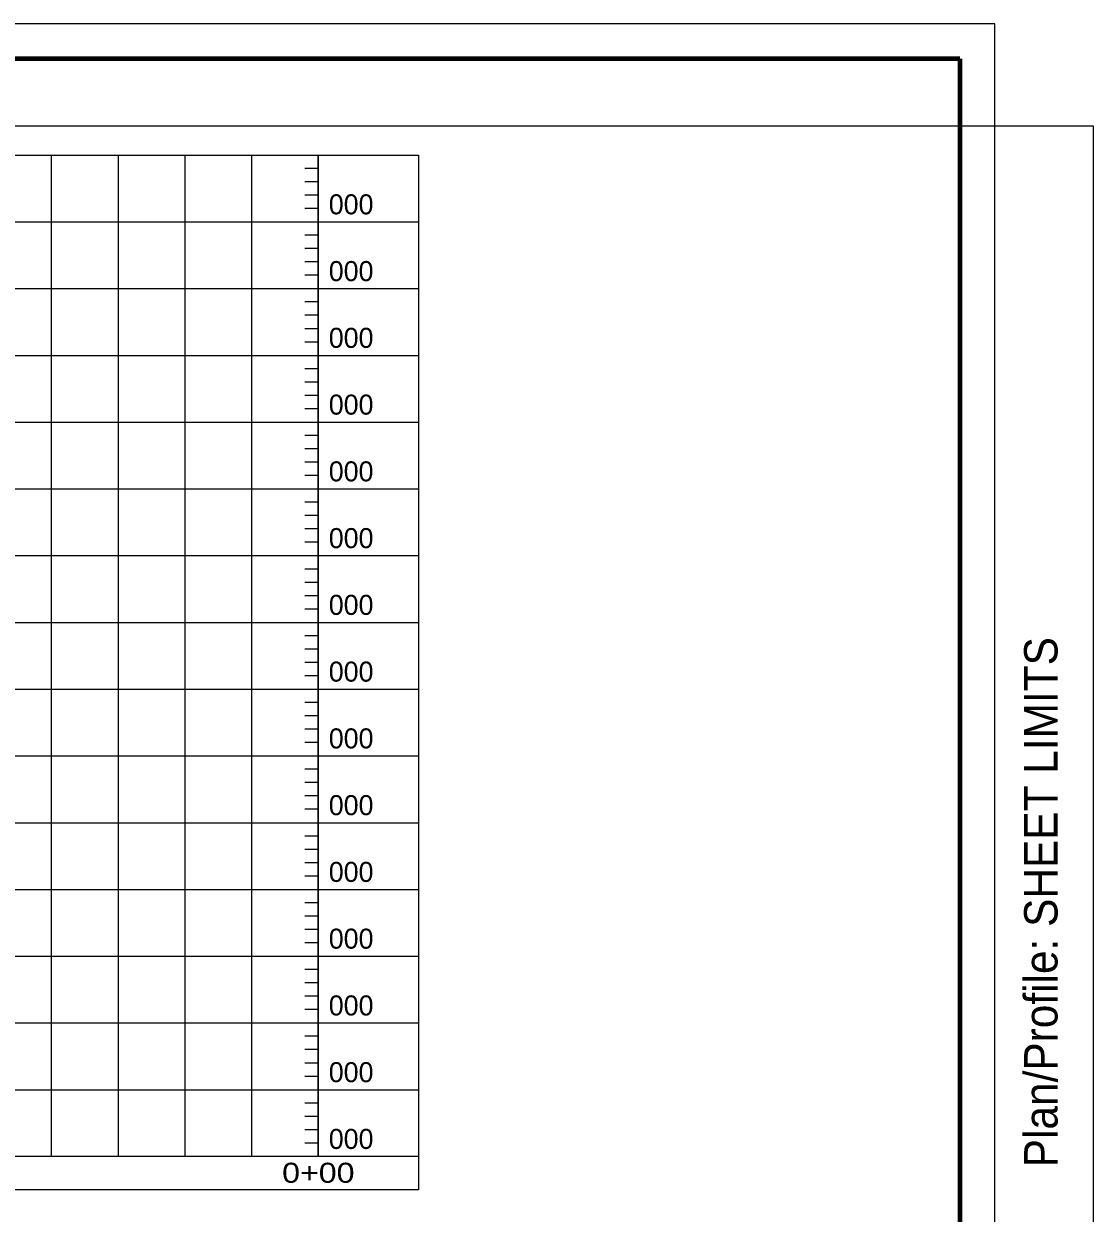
# Model space of a CAD drawing. Extents: x 2246932 to 2264252, y 7095151 to 7098651.
# Drawn here: x 2262650 to 2264252, y 7096869 to 7098651 of the extents above; entities that cross this region are included whole.
import ezdxf
from ezdxf.enums import TextEntityAlignment as Align

# ---------------------------------------------------------------- set-up
doc = ezdxf.new("R2010")
doc.units = 0
doc.header["$LTSCALE"] = 12
for name, color, linetype, lineweight in [('1', 7, 'Continuous', 80), ('62', 7, 'Continuous', 13), ('63', 7, 'Continuous', 25)]:
    doc.layers.add(name, color=color, linetype=linetype, lineweight=lineweight)
doc.layers.add('22', color=7, linetype='Continuous')

msp = doc.modelspace()

# ---------------------------------------------------------------- linework, layer by layer
at = {"layer": '1'}
for q in [(2247157.09, 7098598.35), (2264052.08, 7095203.35)]:
    msp.add_line((2264052.09, 7098598.35), q, dxfattribs=at)
at = {"layer": '1', "lineweight": 25}
msp.add_lwpolyline([(2264104.59, 7095150.85), (2264104.59, 7098650.85), (2247104.59, 7098650.85), (2247104.59, 7095150.85)], dxfattribs=at)
at = {"layer": '62'}
for p, q in [((2247941.45, 7098454.14), (2263241.45, 7098454.14)), ((2262691.45, 7098454.14), (2262691.45, 7096954.14)), ((2262791.45, 7098454.14), (2262791.45, 7096954.14)), ((2262891.45, 7098454.14), (2262891.45, 7096954.14)), ((2262991.45, 7098454.14), (2262991.45, 7096954.14)), ((2263091.45, 7096954.14), (2263091.45, 7098454.14)), ((2263091.45, 7098454.14), (2263091.45, 7096954.14)), ((2263241.45, 7098454.14), (2263241.45, 7097654.14)), ((2263091.45, 7098434.14), (2263071.45, 7098434.14)), ((2263091.45, 7098414.14), (2263071.45, 7098414.14)), ((2263091.45, 7098394.14), (2263071.45, 7098394.14)), ((2263091.45, 7098374.14), (2263071.45, 7098374.14)), ((2263091.45, 7098334.14), (2263071.45, 7098334.14)), ((2263091.45, 7098314.14), (2263071.45, 7098314.14)), ((2263091.45, 7098294.14), (2263071.45, 7098294.14)), ((2263091.45, 7098274.14), (2263071.45, 7098274.14)), ((2263091.45, 7098234.14), (2263071.45, 7098234.14)), ((2263091.45, 7098214.14), (2263071.45, 7098214.14)), ((2263091.45, 7098194.14), (2263071.45, 7098194.14)), ((2263091.45, 7098174.14), (2263071.45, 7098174.14)), ((2263091.45, 7098134.14), (2263071.45, 7098134.14)), ((2263091.45, 7098114.14), (2263071.45, 7098114.14)), ((2263091.45, 7098094.14), (2263071.45, 7098094.14)), ((2263091.45, 7098074.14), (2263071.45, 7098074.14)), ((2263091.45, 7098034.14), (2263071.45, 7098034.14)), ((2263091.45, 7098014.14), (2263071.45, 7098014.14)), ((2263091.45, 7097994.14), (2263071.45, 7097994.14)), ((2263091.45, 7097974.14), (2263071.45, 7097974.14)), ((2263091.45, 7097934.14), (2263071.45, 7097934.14)), ((2263091.45, 7097914.14), (2263071.45, 7097914.14)), ((2263091.45, 7097894.14), (2263071.45, 7097894.14)), ((2263091.45, 7097874.14), (2263071.45, 7097874.14)), ((2263091.45, 7097834.14), (2263071.45, 7097834.14)), ((2263091.45, 7097814.14), (2263071.45, 7097814.14)), ((2263091.45, 7097794.14), (2263071.45, 7097794.14)), ((2263091.45, 7097774.14), (2263071.45, 7097774.14)), ((2263091.45, 7097734.14), (2263071.45, 7097734.14)), ((2263091.45, 7097714.14), (2263071.45, 7097714.14)), ((2263091.45, 7097694.14), (2263071.45, 7097694.14)), ((2263091.45, 7097674.14), (2263071.45, 7097674.14)), ((2263241.45, 7097654.14), (2263241.45, 7096904.14)), ((2263091.45, 7097634.14), (2263071.45, 7097634.14)), ((2263091.45, 7097614.14), (2263071.45, 7097614.14)), ((2263091.45, 7097594.14), (2263071.45, 7097594.14)), ((2263091.45, 7097574.14), (2263071.45, 7097574.14)), ((2263091.45, 7097534.14), (2263071.45, 7097534.14)), ((2263091.45, 7097514.14), (2263071.45, 7097514.14)), ((2263091.45, 7097494.14), (2263071.45, 7097494.14)), ((2263091.45, 7097474.14), (2263071.45, 7097474.14)), ((2263091.45, 7097434.14), (2263071.45, 7097434.14)), ((2263091.45, 7097414.14), (2263071.45, 7097414.14)), ((2263091.45, 7097394.14), (2263071.45, 7097394.14)), ((2263091.45, 7097374.14), (2263071.45, 7097374.14)), ((2263091.45, 7097334.14), (2263071.45, 7097334.14)), ((2263091.45, 7097314.14), (2263071.45, 7097314.14)), ((2263091.45, 7097294.14), (2263071.45, 7097294.14)), ((2263091.45, 7097274.14), (2263071.45, 7097274.14)), ((2263091.45, 7097234.14), (2263071.45, 7097234.14)), ((2263091.45, 7097214.14), (2263071.45, 7097214.14)), ((2263091.45, 7097194.14), (2263071.45, 7097194.14)), ((2263091.45, 7097174.14), (2263071.45, 7097174.14)), ((2263091.45, 7097134.14), (2263071.45, 7097134.14)), ((2263091.45, 7097114.14), (2263071.45, 7097114.14)), ((2263091.45, 7097094.14), (2263071.45, 7097094.14)), ((2263091.45, 7097074.14), (2263071.45, 7097074.14)), ((2263091.45, 7097034.14), (2263071.45, 7097034.14)), ((2263091.45, 7097014.14), (2263071.45, 7097014.14)), ((2263091.45, 7096994.14), (2263071.45, 7096994.14)), ((2263091.45, 7096974.14), (2263071.45, 7096974.14)), ((2263241.45, 7096954.14), (2247941.45, 7096954.14)), ((2263241.45, 7096904.14), (2247941.45, 7096904.14))]:
    msp.add_line(p, q, dxfattribs=at)
for points in [[(2248091.45, 7098354.14), (2263091.45, 7098354.14), (2263241.45, 7098354.14)], [(2248091.45, 7098254.14), (2263091.45, 7098254.14), (2263241.45, 7098254.14)], [(2248091.45, 7098154.14), (2263091.45, 7098154.14), (2263241.45, 7098154.14)], [(2248091.45, 7098054.14), (2263091.45, 7098054.14), (2263241.45, 7098054.14)], [(2248091.45, 7097954.14), (2263091.45, 7097954.14), (2263241.45, 7097954.14)], [(2248091.45, 7097854.14), (2263091.45, 7097854.14), (2263241.45, 7097854.14)], [(2248091.45, 7097754.14), (2263091.45, 7097754.14), (2263241.45, 7097754.14)], [(2248091.45, 7097654.14), (2263091.45, 7097654.14), (2263241.45, 7097654.14)], [(2248091.45, 7097554.14), (2263091.45, 7097554.14), (2263241.45, 7097554.14)], [(2248091.45, 7097454.14), (2263091.45, 7097454.14), (2263241.45, 7097454.14)], [(2248091.45, 7097354.14), (2263091.45, 7097354.14), (2263241.45, 7097354.14)], [(2248091.45, 7097254.14), (2263091.45, 7097254.14), (2263241.45, 7097254.14)], [(2248091.45, 7097154.14), (2263091.45, 7097154.14), (2263241.45, 7097154.14)], [(2248091.45, 7097054.14), (2263091.45, 7097054.14), (2263241.45, 7097054.14)]]:
    msp.add_lwpolyline(points, dxfattribs=at)
at = {"layer": '63'}
msp.add_lwpolyline([(2264252.09, 7095298.54), (2262549.93, 7095298.54), (2262549.93, 7098498.04), (2264252.09, 7098498.04)], close=True, dxfattribs=at)

# ---------------------------------------------------------------- texts
at = {"layer": '22'}
for p in [(2263107.14, 7098365.4), (2263107.14, 7098265.4), (2263107.14, 7098165.4), (2263107.14, 7098065.4), (2263107.14, 7097965.4), (2263107.14, 7097865.4), (2263107.14, 7097765.4), (2263107.14, 7097665.4), (2263107.13, 7097565.4), (2263107.13, 7097465.4), (2263107.13, 7097365.4), (2263107.13, 7097265.4), (2263107.13, 7097165.4), (2263107.13, 7097065.4), (2263107.13, 7096965.4)]:
    msp.add_text('000', height=30, dxfattribs=at).set_placement(p)
at = {"layer": '22', "width": 1.2}
msp.add_text('0+00', height=30, dxfattribs=at).set_placement((2263091.44, 7096914.74), align=Align.CENTER)
msp.add_text('0+00', height=30, dxfattribs=at).set_placement((2263091.44, 7096914.74), align=Align.CENTER)
at = {"layer": '63', "width": 0.95}
msp.add_text('Plan/Profile: SHEET LIMITS', height=50, rotation=90, dxfattribs=at).set_placement((2264198.63, 7097335.05), align=Align.CENTER)

doc.saveas('drawing.dxf')
